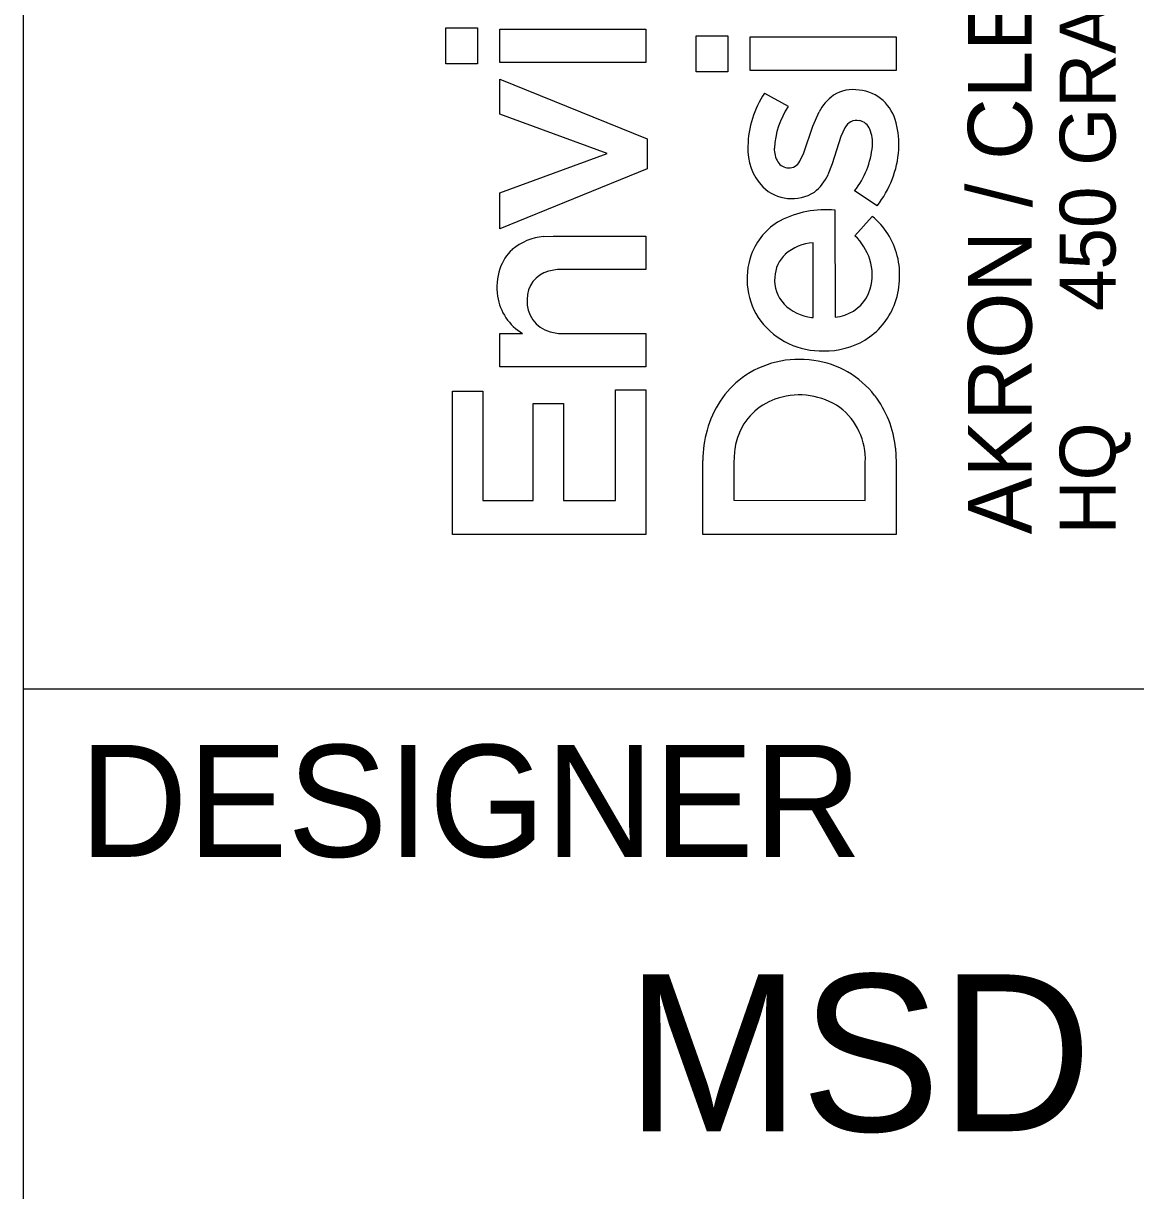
# Model space of a CAD drawing. Extents: x -7 to 3400, y -220 to 22.
# Drawn here: x 32 to 32.993, y 2.552 to 3.594 of the extents above; entities that cross this region are included whole.
import ezdxf

# ---------------------------------------------------------------- set-up
doc = ezdxf.new("R2010")
doc.units = 0
doc.layers.add('SH_Border', color=7, linetype='Continuous')
doc.layers.add('SH_Data', color=7, linetype='Continuous')

msp = doc.modelspace()

# ---------------------------------------------------------------- linework, layer by layer
at = {"layer": 'SH_Border'}
for p, q in [((32, 0.5), (32, 21.5)), ((32, 3), (33.5, 3))]:
    msp.add_line(p, q, dxfattribs=at)
at = {"layer": 'SH_Data'}
for p, q in [((32.3771, 3.5582), (32.3771, 3.5903)), ((32.3771, 3.5903), (32.4054, 3.5903)), ((32.4054, 3.5903), (32.4054, 3.5582)), ((32.4254, 3.5594), (32.4254, 3.5893)), ((32.4254, 3.5893), (32.5557, 3.5893)), ((32.5557, 3.5893), (32.5557, 3.5594)), ((32.6005, 3.5511), (32.6005, 3.5832)), ((32.6005, 3.5832), (32.6289, 3.5832)), ((32.6289, 3.5832), (32.6289, 3.5511)), ((32.6489, 3.5523), (32.6489, 3.5822)), ((32.6489, 3.5822), (32.7792, 3.5822)), ((32.7792, 3.5822), (32.7792, 3.5523)), ((32.4054, 3.5582), (32.3771, 3.5582)), ((32.5557, 3.5594), (32.4254, 3.5594)), ((32.4254, 3.5133), (32.4254, 3.5446)), ((32.4254, 3.5446), (32.5567, 3.4913)), ((32.6289, 3.5511), (32.6005, 3.5511)), ((32.7792, 3.5523), (32.6489, 3.5523)), ((32.6615, 3.5321), (32.6827, 3.5203)), ((32.5212, 3.478), (32.4254, 3.5133)), ((32.7048, 3.5026), (32.7104, 3.5153)), ((32.6967, 3.4787), (32.7048, 3.5026)), ((32.7298, 3.4933), (32.7221, 3.4688)), ((32.7334, 3.501), (32.7298, 3.4933)), ((32.5567, 3.4913), (32.5567, 3.4644)), ((32.4254, 3.4429), (32.5212, 3.478)), ((32.693, 3.4712), (32.6967, 3.4787)), ((32.5567, 3.4644), (32.4254, 3.4109)), ((32.7221, 3.4688), (32.7182, 3.4592)), ((32.4254, 3.4109), (32.4254, 3.4429)), ((32.7621, 3.4314), (32.742, 3.4447)), ((32.7245, 3.4275), (32.7246, 3.3319)), ((32.7423, 3.4046), (32.7577, 3.422)), ((32.4644, 3.404), (32.4729, 3.4044)), ((32.4729, 3.4044), (32.5557, 3.4044)), ((32.5557, 3.4044), (32.5557, 3.3746)), ((32.7049, 3.3318), (32.7049, 3.3983)), ((32.5557, 3.3746), (32.4814, 3.3746)), ((32.7036, 3.3317), (32.7049, 3.3318)), ((32.4254, 3.2875), (32.4254, 3.3173)), ((32.4254, 3.3173), (32.4455, 3.3173)), ((32.4822, 3.3173), (32.5557, 3.3173)), ((32.5557, 3.3173), (32.5557, 3.2876)), ((32.5557, 3.2876), (32.4254, 3.2875)), ((32.383, 3.1379), (32.383, 3.266)), ((32.383, 3.266), (32.4101, 3.266)), ((32.4101, 3.266), (32.4101, 3.1683)), ((32.5286, 3.1683), (32.5286, 3.2672)), ((32.5286, 3.2672), (32.5557, 3.2672)), ((32.5557, 3.2672), (32.5557, 3.1379)), ((32.455, 3.1683), (32.455, 3.2549)), ((32.455, 3.2549), (32.4822, 3.2549)), ((32.4822, 3.2549), (32.4822, 3.1683)), ((32.6347, 3.2118), (32.6341, 3.2023)), ((32.7785, 3.215), (32.7792, 3.2021)), ((32.6064, 3.138), (32.6064, 3.204)), ((32.6341, 3.2023), (32.6341, 3.1684)), ((32.7515, 3.1683), (32.7515, 3.2024)), ((32.7792, 3.2021), (32.7792, 3.138)), ((32.4101, 3.1683), (32.455, 3.1683)), ((32.4822, 3.1683), (32.5286, 3.1683)), ((32.6341, 3.1684), (32.7515, 3.1683)), ((32.5557, 3.1379), (32.383, 3.1379)), ((32.7792, 3.138), (32.6064, 3.138))]:
    msp.add_line(p, q, dxfattribs=at)
for points in [[(32.3771, 3.5582), (32.3771, 3.5903), (32.4054, 3.5903), (32.4054, 3.5582)], [(32.4254, 3.5594), (32.4254, 3.5893), (32.5557, 3.5893), (32.5557, 3.5594)], [(32.6005, 3.5511), (32.6005, 3.5832), (32.6289, 3.5832), (32.6289, 3.5511)], [(32.6489, 3.5523), (32.6489, 3.5822), (32.7792, 3.5822), (32.7792, 3.5523)], [(32.4254, 3.4109), (32.4254, 3.4429), (32.5212, 3.478), (32.4254, 3.5133), (32.4254, 3.5446), (32.5567, 3.4913), (32.5567, 3.4644)], [(32.383, 3.1379), (32.383, 3.266), (32.4101, 3.266), (32.4101, 3.1683), (32.455, 3.1683), (32.455, 3.2549), (32.4822, 3.2549), (32.4822, 3.1683), (32.5286, 3.1683), (32.5286, 3.2672), (32.5557, 3.2672), (32.5557, 3.1379)]]:
    msp.add_lwpolyline(points, close=True, dxfattribs=at)
for points in [[(32.6615, 3.5321), (32.6827, 3.5203)], [(32.693, 3.4712), (32.6967, 3.4787), (32.7048, 3.5026), (32.7104, 3.5153)], [(32.7334, 3.501), (32.7298, 3.4933), (32.7221, 3.4688), (32.7182, 3.4592)], [(32.7621, 3.4314), (32.742, 3.4447)], [(32.7245, 3.4275), (32.7246, 3.3319)], [(32.7423, 3.4046), (32.7577, 3.422)], [(32.4644, 3.404), (32.4729, 3.4044), (32.5557, 3.4044), (32.5557, 3.3746), (32.4814, 3.3746)], [(32.7036, 3.3317), (32.7049, 3.3318), (32.7049, 3.3983)], [(32.4254, 3.2875), (32.4254, 3.3173), (32.4455, 3.3173)], [(32.4822, 3.3173), (32.5557, 3.3173), (32.5557, 3.2876), (32.4254, 3.2875)], [(32.7785, 3.215), (32.7792, 3.2021), (32.7792, 3.138), (32.6064, 3.138)], [(32.6347, 3.2118), (32.6341, 3.2023), (32.6341, 3.1684), (32.7515, 3.1683), (32.7515, 3.2024)], [(32.6064, 3.138), (32.6064, 3.204)]]:
    msp.add_lwpolyline(points, dxfattribs=at)
for centre, radius, start, end in [((32.7406, 3.5026), 0.0326, 80.1719, 122.5197), ((32.7406, 3.5026), 0.0326, 80.1719, 122.5197), ((32.7428, 3.4982), 0.0367, 47.7934, 84.6892), ((32.7428, 3.4982), 0.0367, 47.7934, 84.6892), ((32.7364, 3.4826), 0.0897, 146.531, 178.7571), ((32.7364, 3.4826), 0.0897, 146.531, 178.7571), ((32.7466, 3.4971), 0.0405, 125.5118, 153.4159), ((32.7466, 3.4971), 0.0405, 125.5118, 153.4159), ((32.7379, 3.4946), 0.0427, 14.9966, 46.2063), ((32.7379, 3.4946), 0.0427, 14.9966, 46.2063), ((32.7452, 3.4789), 0.0749, 146.5112, 176.9101), ((32.7452, 3.4789), 0.0749, 146.5112, 176.9101), ((32.7438, 3.4963), 0.0114, 76.6609, 155.7053), ((32.7438, 3.4963), 0.0114, 76.6609, 155.7053), ((32.744, 3.4951), 0.0126, 21.5098, 78.5262), ((32.744, 3.4951), 0.0126, 21.5098, 78.5262), ((32.7104, 3.4867), 0.0712, 355.8306, 15.3914), ((32.7104, 3.4867), 0.0712, 355.8306, 15.3914), ((32.7259, 3.4877), 0.0321, 354.5726, 22.068), ((32.7259, 3.4877), 0.0321, 354.5726, 22.068), ((32.6967, 3.4824), 0.0501, 177.5366, 222.7932), ((32.6967, 3.4824), 0.0501, 177.5366, 222.7932), ((32.6931, 3.4823), 0.0228, 178.4747, 211.0868), ((32.6931, 3.4823), 0.0228, 178.4747, 211.0868), ((32.6825, 3.4915), 0.0757, 321.811, 354.7969), ((32.6825, 3.4915), 0.0757, 321.811, 354.7969), ((32.6895, 3.4882), 0.0922, 321.9777, 355.8738), ((32.6895, 3.4882), 0.0922, 321.9777, 355.8738), ((32.6833, 3.4767), 0.0115, 212.2368, 268.3777), ((32.6833, 3.4767), 0.0115, 212.2368, 268.3777), ((32.6834, 3.4759), 0.0107, 267.716, 333.7337), ((32.6834, 3.4759), 0.0107, 267.716, 333.7337), ((32.681, 3.4758), 0.0408, 308.0877, 335.9874), ((32.681, 3.4758), 0.0408, 308.0877, 335.9874), ((32.686, 3.4753), 0.0375, 225.9854, 302.4797), ((32.686, 3.4753), 0.0375, 225.9854, 302.4797), ((32.7152, 3.3441), 0.0838, 83.615, 118.2876), ((32.7152, 3.3441), 0.0838, 83.615, 118.2876), ((32.7174, 3.3717), 0.0644, 13.5336, 51.3615), ((32.7174, 3.3717), 0.0644, 13.5336, 51.3615), ((32.7024, 3.3691), 0.0558, 118.8308, 160.6244), ((32.7024, 3.3691), 0.0558, 118.8308, 160.6244), ((32.4687, 3.3543), 0.0499, 94.9696, 130.2225), ((32.4687, 3.3543), 0.0499, 94.9696, 130.2225), ((32.7038, 3.3656), 0.0549, 19.0357, 45.4406), ((32.7038, 3.3656), 0.0549, 19.0357, 45.4406), ((32.4635, 3.3626), 0.0402, 132.2219, 161.6818), ((32.4635, 3.3626), 0.0402, 132.2219, 161.6818), ((32.7005, 3.3663), 0.0298, 132.9851, 177.179), ((32.7005, 3.3663), 0.0298, 132.9851, 177.179), ((32.7079, 3.3561), 0.0424, 94.008, 130.8817), ((32.7079, 3.3561), 0.0424, 94.008, 130.8817), ((32.7104, 3.3661), 0.0644, 160.5201, 215.7831), ((32.7104, 3.3661), 0.0644, 160.5201, 215.7831), ((32.7107, 3.3697), 0.047, 344.6059, 17.007), ((32.7107, 3.3697), 0.047, 344.6059, 17.007), ((32.7064, 3.3692), 0.0758, 339.3542, 13.3785), ((32.7064, 3.3692), 0.0758, 339.3542, 13.3785), ((32.4787, 3.3582), 0.056, 162.2736, 187.7919), ((32.4787, 3.3582), 0.056, 162.2736, 187.7919), ((32.4748, 3.3487), 0.025, 103.6865, 182.2187), ((32.4748, 3.3487), 0.025, 103.6865, 182.2187), ((32.4811, 3.3286), 0.046, 89.6049, 105.3284), ((32.4811, 3.3286), 0.046, 89.6049, 105.3284), ((32.7017, 3.365), 0.0311, 175.0013, 223.283), ((32.7017, 3.365), 0.0311, 175.0013, 223.283), ((32.7224, 3.3671), 0.035, 288.0077, 343.5508), ((32.7224, 3.3671), 0.035, 288.0077, 343.5508), ((32.4703, 3.358), 0.0476, 188.962, 238.7037), ((32.4703, 3.358), 0.0476, 188.962, 238.7037), ((32.4773, 3.3456), 0.0276, 175.5854, 255.1439), ((32.4773, 3.3456), 0.0276, 175.5854, 255.1439), ((32.7089, 3.3736), 0.0423, 225.0619, 262.7974), ((32.7089, 3.3736), 0.0423, 225.0619, 262.7974), ((32.7189, 3.3652), 0.0626, 300.9427, 338.7323), ((32.7189, 3.3652), 0.0626, 300.9427, 338.7323), ((32.7125, 3.3705), 0.0687, 217.7452, 271.6543), ((32.7125, 3.3705), 0.0687, 217.7452, 271.6543), ((32.7247, 3.3522), 0.0202, 269.7003, 294.8711), ((32.7247, 3.3522), 0.0202, 269.7003, 294.8711), ((32.4818, 3.3595), 0.0422, 254.0916, 270.5284), ((32.4818, 3.3595), 0.0422, 254.0916, 270.5284), ((32.7155, 3.3724), 0.0706, 269.2048, 300.3341), ((32.7155, 3.3724), 0.0706, 269.2048, 300.3341), ((32.6923, 3.2079), 0.0864, 81.194, 125.9984), ((32.6923, 3.2079), 0.0864, 81.194, 125.9984), ((32.6946, 3.2113), 0.0827, 37.8521, 82.402), ((32.6946, 3.2113), 0.0827, 37.8521, 82.402), ((32.6939, 3.2089), 0.0865, 127.2362, 165.148), ((32.6939, 3.2089), 0.0865, 127.2362, 165.148), ((32.6889, 3.2078), 0.054, 106.1881, 157.3861), ((32.6889, 3.2078), 0.054, 106.1881, 157.3861), ((32.6928, 3.1986), 0.0639, 55.6727, 107.2093), ((32.6928, 3.1986), 0.0639, 55.6727, 107.2093), ((32.6859, 3.2057), 0.0931, 5.7333, 37.304), ((32.6859, 3.2057), 0.0931, 5.7333, 37.304), ((32.6929, 3.205), 0.0587, 357.4662, 52.2665), ((32.6929, 3.205), 0.0587, 357.4662, 52.2665), ((32.7143, 3.2028), 0.1078, 164.7861, 179.3704), ((32.7143, 3.2028), 0.1078, 164.7861, 179.3704), ((32.6983, 3.2039), 0.0641, 157.3571, 172.9275), ((32.6983, 3.2039), 0.0641, 157.3571, 172.9275)]:
    msp.add_arc(centre, radius, start, end, dxfattribs=at)

# ---------------------------------------------------------------- texts
for s, height, p in [('450 GRANT ST., AKRON, OH  44311', 0.049846, (32.9749, 3.3374)), ('AKRON / CLEVELAND / COLUMBUS', 0.056969, (32.9001, 3.138)), ('HQ ', 0.04985, (32.9749, 3.138))]:
    msp.add_text(s, height=height, rotation=90, dxfattribs=at).set_placement(p)
for s, height, p in [('DESIGNER', 0.1, (32.05, 2.85)), ('MSD', 0.14, (32.5379, 2.605))]:
    msp.add_text(s, height=height, dxfattribs=at).set_placement(p)

doc.saveas('drawing.dxf')
